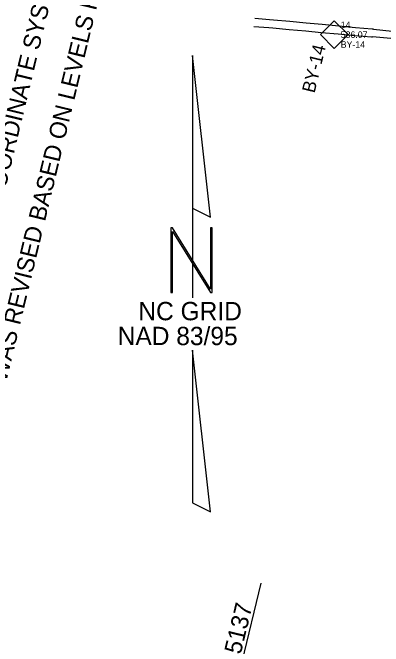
# Model space of a CAD drawing. Extents: x 1649669 to 1659218, y 588594 to 607900.
# Drawn here: x 1652859 to 1653992, y 599457 to 601392 of the extents above; entities that cross this region are included whole.
import ezdxf

# ---------------------------------------------------------------- set-up
doc = ezdxf.new("R2010")
doc.units = 0
for name, color, linetype in [('CTL North Arrow NAD 83 95 CELL', 7, 'Continuous'), ('CTL Sheet Notes CELL', 7, 'Continuous'), ('CTL Supplemental Horizontal and Vertical CELL', 7, 'Continuous'), ('CTL Supplemental Horizontal and Vertical Cogo Comment', 7, 'Continuous'), ('CTL Supplemental Horizontal and Vertical Cogo Elevation', 7, 'Continuous'), ('CTL Supplemental Horizontal and Vertical Cogo Number', 7, 'Continuous'), ('CTL Supplemental Horizontal and Vertical Text', 7, 'Continuous'), ('Default', 7, 'Continuous'), ('Exist Roads EOP', 7, 'Continuous'), ('Sheet Data Field CELL', 7, 'Continuous')]:
    doc.layers.add(name, color=color, linetype=linetype)

# ---------------------------------------------------------------- blocks, each defined once
blk = doc.blocks.new('CTL NORTH ARROW NAD 83 95')
at = {"layer": 'CTL North Arrow NAD 83 95 CELL'}
for points in [[(-0.003, 1.7458), (-0.003, 0.5793), (0.1345, 0.5105)], [(-0.1675, -0.0653), (-0.1537, -0.0653), (-0.1537, 0.4012), (0.1345, -0.0653), (0.1482, -0.0653), (0.1482, 0.4285), (0.1345, 0.4285), (0.1345, -0.038), (-0.1537, 0.4285), (-0.1675, 0.4285)], [(-0.003, -1.671), (0.1345, -1.7392), (-0.003, -0.5045)]]:
    blk.add_lwpolyline(points, close=True, dxfattribs=at)
blk.add_lwpolyline([(-0.003, 0.5793), (-0.003, -0.1067)], dxfattribs=at)
for s, p in [('NC GRID', (-0.4154, -0.2767)), ('NAD 83/95', (-0.5731, -0.4667))]:
    blk.add_text(s, height=0.14, dxfattribs=at).set_placement(p)

msp = doc.modelspace()

# ---------------------------------------------------------------- linework, layer by layer
at = {"layer": 'CTL Supplemental Horizontal and Vertical CELL'}
msp.add_line((1653841.4, 601324.4), (1653841.4, 601324.4), dxfattribs=at)
msp.add_lwpolyline([(1653799.7, 601324.5), (1653841.6, 601366.5), (1653883.6, 601324.5), (1653841.7, 601282.5)], close=True, dxfattribs=at)
at = {"layer": 'Default'}
msp.add_line((1653425.8, 598852.2), (1653618.3, 599649.4), dxfattribs=at)
at = {"layer": 'Exist Roads EOP'}
for p, q in [((1653643.4, 601369.9), (1653598.9, 601373.9)), ((1653595.9, 601349.9), (1653641.7, 601346.1))]:
    msp.add_line(p, q, dxfattribs=at)
for points in [[(1653961.6, 601340.9), (1653957.5, 601341.3), (1653906.6, 601345.8), (1653855.5, 601350.5), (1653805, 601355.2), (1653755.8, 601359.7), (1653705.9, 601364.3), (1653655.6, 601368.8), (1653643.4, 601369.9)], [(1653641.7, 601346.1), (1653654, 601345), (1653703.7, 601340.5), (1653754.3, 601335.9), (1653802.1, 601331.4), (1653853.9, 601326.6), (1653904, 601322), (1653955, 601318), (1653958.8, 601317.5)], [(1653961.6, 601340.9), (1654019, 601335.5), (1654066.8, 601331), (1654116.7, 601325.7), (1654156.8, 601321), (1654206.4, 601315.2), (1654235.6, 601311.2), (1654284.3, 601304.6), (1654317.9, 601299.5), (1654322.7, 601299)], [(1654143.3, 601266.5), (1654142.3, 601273.1), (1654138.6, 601280.8), (1654133.7, 601288), (1654126.9, 601294), (1654114.8, 601301), (1654107.3, 601302.9), (1654065.5, 601307.5), (1654014.2, 601312.6), (1653958.8, 601317.5)]]:
    msp.add_lwpolyline(points, dxfattribs=at)

# ---------------------------------------------------------------- block references
at = {"layer": 'CTL North Arrow NAD 83 95 CELL', "xscale": 399.99999999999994, "yscale": 399.9999999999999}
msp.add_blockref('CTL NORTH ARROW NAD 83 95', (1653409.4, 600563), dxfattribs=at)

# ---------------------------------------------------------------- texts
at = {"layer": 'CTL Sheet Notes CELL'}
for s, p in [('3.    THIS PROJECT USES THE SAME DATUM AND COORDINATE SYSTEM AS TIP PROJECT U-3300B.', (1652431.3, 599171.9)), ('4.    THE ELEVATION OF U3300B-1 WAS REVISED BASED ON LEVELS RUN FOR B-5137 PROJECT.', (1652568.4, 599138.8))]:
    msp.add_text(s, height=52.174, rotation=76.4261, dxfattribs=at).set_placement(p)
at = {"layer": 'CTL Supplemental Horizontal and Vertical Cogo Comment'}
msp.add_text('BY-14', height=20, dxfattribs=at).set_placement((1653861.4, 601284.4))
at = {"layer": 'CTL Supplemental Horizontal and Vertical Cogo Elevation'}
msp.add_text('586.07', height=20, dxfattribs=at).set_placement((1653861.4, 601314.4))
at = {"layer": 'CTL Supplemental Horizontal and Vertical Cogo Number'}
msp.add_text('14', height=20, dxfattribs=at).set_placement((1653861.4, 601344.4))
at = {"layer": 'CTL Supplemental Horizontal and Vertical Text'}
msp.add_text('BY-14', height=40, rotation=76.4261, dxfattribs=at).set_placement((1653781.3, 601144.2))
at = {"layer": 'Sheet Data Field CELL'}
msp.add_text('END PROJECT B-5137', height=52.501, rotation=76.4261, dxfattribs=at).set_placement((1653418.5, 598861.2))

doc.saveas('drawing.dxf')
